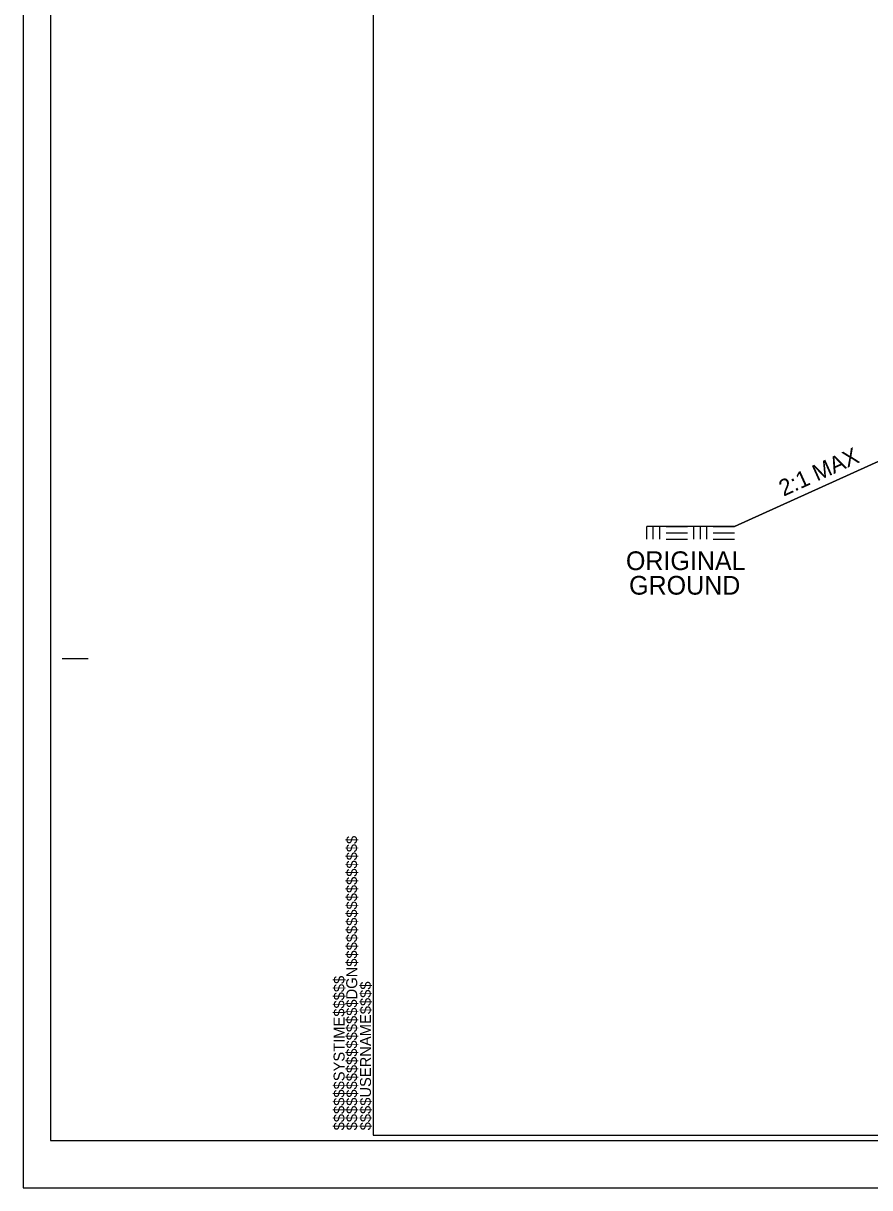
# Model space of a CAD drawing. Extents: x 9470 to 10081, y 10104 to 10463.
# Drawn here: x 9816.8 to 9873.4, y 10104 to 10181.8 of the extents above; entities that cross this region are included whole.
import ezdxf

# ---------------------------------------------------------------- set-up
doc = ezdxf.new("R2010")
doc.units = 0
for name, color, linetype in [('Default', 7, 'Continuous'), ('Old_Level_1', 7, 'Continuous'), ('Old_Level_11', 7, 'Continuous'), ('Sheet Cutting Line CELL', 7, 'Continuous'), ('Sheet Plot Border Inside CELL', 7, 'Continuous'), ('Sheet Plot Border Outside CELL', 7, 'Continuous'), ('Sheet Typical CELL', 7, 'Continuous'), ('Typical Hinge Slope Arterial CELL', 7, 'Continuous'), ('Typical Slope Point Local CELL', 7, 'Continuous')]:
    doc.layers.add(name, color=color, linetype=linetype)

msp = doc.modelspace()

# ---------------------------------------------------------------- linework, layer by layer
at = {"layer": 'Old_Level_1'}
for p, q in [((9864.356, 10148.157), (9858.493, 10148.157)), ((9858.493, 10147.299), (9858.493, 10148.157)), ((9858.922, 10147.299), (9858.922, 10148.157)), ((9859.351, 10147.299), (9859.351, 10148.157)), ((9859.78, 10148.157), (9861.21, 10148.157)), ((9861.639, 10147.299), (9861.639, 10148.157)), ((9862.068, 10147.299), (9862.068, 10148.157)), ((9862.497, 10147.299), (9862.497, 10148.157)), ((9862.926, 10148.157), (9864.356, 10148.157)), ((9859.78, 10147.728), (9861.21, 10147.728)), ((9859.78, 10147.299), (9861.21, 10147.299)), ((9862.926, 10147.728), (9864.356, 10147.728)), ((9862.926, 10147.299), (9864.356, 10147.299))]:
    msp.add_line(p, q, dxfattribs=at)
at = {"layer": 'Sheet Cutting Line CELL'}
for p, q in [((9816.836, 10257.984), (9816.836, 10103.984)), ((9816.836, 10103.984), (10052.596, 10103.984))]:
    msp.add_line(p, q, dxfattribs=at)
at = {"layer": 'Sheet Plot Border Inside CELL'}
msp.add_lwpolyline([(10051.966, 10254.841), (9818.656, 10254.841), (9818.656, 10107.127), (10051.966, 10107.127)], close=True, dxfattribs=at)
at = {"layer": 'Sheet Plot Border Outside CELL'}
msp.add_lwpolyline([(10052.596, 10257.984), (9816.836, 10257.984), (9816.836, 10103.984), (10052.596, 10103.984)], close=True, dxfattribs=at)
at = {"layer": 'Sheet Typical CELL'}
for p, q in [((9819.426, 10139.334), (9821.176, 10139.334)), ((9840.216, 10107.484), (9840.216, 10107.484)), ((9840.216, 10107.484), (9840.216, 10107.484)), ((9840.216, 10107.484), (9840.216, 10107.484)), ((9840.216, 10107.484), (9840.216, 10107.484)), ((9840.216, 10107.484), (9840.216, 10107.484)), ((9840.216, 10107.484), (9840.216, 10107.484))]:
    msp.add_line(p, q, dxfattribs=at)
msp.add_lwpolyline([(10050.216, 10254.484), (9840.216, 10254.484), (9840.216, 10107.484), (10050.216, 10107.484)], close=True, dxfattribs=at)
msp.add_lwpolyline([(9845.466, 10107.484), (9845.466, 10107.484)], dxfattribs=at)
at = {"layer": 'Typical Hinge Slope Arterial CELL'}
msp.add_line((9876.56, 10153.675), (9864.356, 10148.157), dxfattribs=at)
at = {"layer": 'Typical Slope Point Local CELL'}
msp.add_line((9864.356, 10148.157), (9876.56, 10153.675), dxfattribs=at)

# ---------------------------------------------------------------- texts
at = {"layer": 'Default'}
msp.add_text('2:1 MAX', height=1.1, rotation=24.32711, dxfattribs=at).set_placement((9867.626, 10150.145))
at = {"layer": 'Old_Level_11'}
for s, p in [('ORIGINAL', (9857.095, 10145.243)), ('GROUND', (9857.305, 10143.603))]:
    msp.add_text(s, height=1.25, rotation=359.99874, dxfattribs=at).set_placement(p)
at = {"layer": 'Sheet Typical CELL'}
for s, p in [('$$$$$$$$$$$$$$$$DGN$$$$$$$$$$$$$$$$', (9839.145, 10107.815)), ('$$$$$$SYSTIME$$$$$', (9838.298, 10107.815)), ('$$$$USERNAME$$$$', (9840.065, 10107.817))]:
    msp.add_text(s, height=0.735, rotation=90, dxfattribs=at).set_placement(p)

doc.saveas('drawing.dxf')
